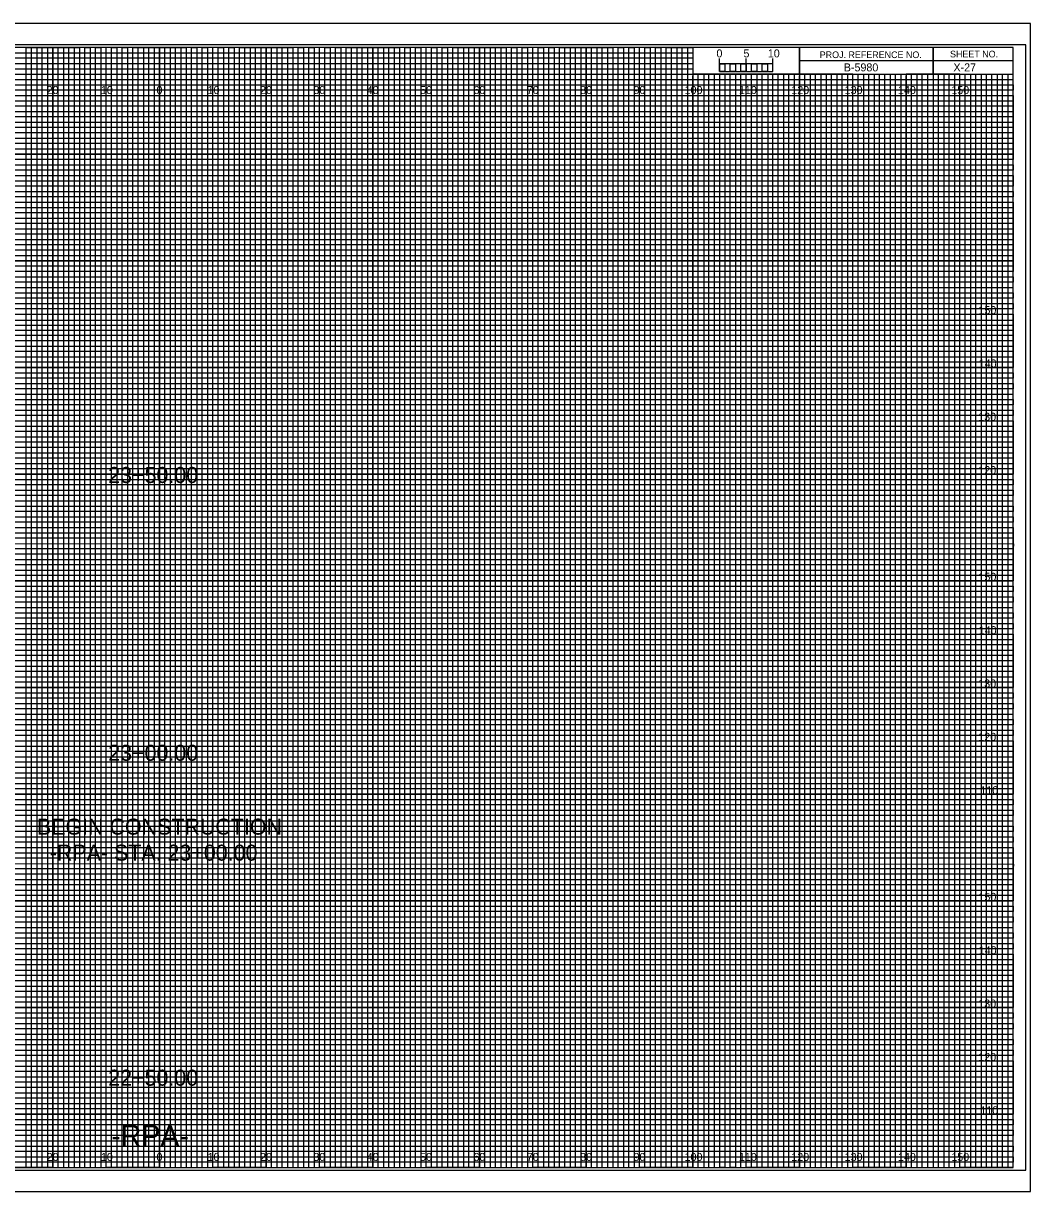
# Model space of a CAD drawing. Extents: x -13 to 323, y -5 to 1974.
# Drawn here: x 134.5 to 323.3, y 655.5 to 874.5 of the extents above; entities that cross this region are included whole.
import ezdxf

# ---------------------------------------------------------------- set-up
doc = ezdxf.new("R2010")
doc.units = 0
for name, color, linetype in [('Exist Cross Section Cell', 7, 'Continuous'), ('Exist XS Center Line Elevation Label', 7, 'Continuous'), ('Exist XS Ground Line', 7, 'Continuous'), ('Prop CMT Bridge Girder Bottom Critical Point Inside', 7, 'Continuous'), ('Prop CMT Guardrail Graphics', 7, 'Continuous'), ('Prop CMT Guardrail Widen Shoulder', 7, 'Continuous'), ('Prop CMT Pvmt Course 1', 7, 'Continuous'), ('Prop CMT Pvmt Course 2', 7, 'Continuous'), ('Prop CMT Pvmt Course 3', 7, 'Continuous'), ('Prop CMT Pvmt Surface', 7, 'Continuous'), ('Prop CMT Pvmt Surface Shoulder', 7, 'Continuous'), ('Prop CMT Shld Paved Course 1', 7, 'Continuous'), ('Prop CMT Shld Paved Course 2', 7, 'Continuous'), ('Prop CMT Shld Paved Course 3', 7, 'Continuous'), ('Prop CMT Slope Grass', 7, 'Continuous'), ('Prop CMT Subgrade Earthwork', 7, 'Continuous'), ('Scratch_Level_1', 7, 'Continuous')]:
    doc.layers.add(name, color=color, linetype=linetype)

msp = doc.modelspace()

# ---------------------------------------------------------------- linework, layer by layer
at = {"layer": 'Exist XS Center Line Elevation Label'}
for points in [[(125, 660), (135, 660), (135, 870), (145, 870), (145, 660), (155, 660), (155, 870), (165, 870), (165, 660), (175, 660), (175, 870), (185, 870), (185, 660), (195, 660), (195, 870), (205, 870), (205, 660), (215, 660), (215, 870), (225, 870), (225, 660), (235, 660), (235, 870), (245, 870), (245, 660), (255, 660), (255, 870), (259.93, 870), (260, 870), (260, 865), (264.99, 865), (264.99, 660), (275, 660), (275, 865), (285, 865), (285, 660), (295, 660), (295, 865), (305, 865), (305, 660), (315, 660), (315, 865)], [(0, 865), (275, 865)], [(0, 845), (320, 845), (320, 855), (0, 855)], [(0, 825), (320, 825), (320, 835), (0, 835)], [(0, 805), (320, 805), (320, 815), (0, 815)], [(0, 785), (320, 785), (320, 795), (0, 795)], [(0, 765), (320, 765), (320, 775), (0, 775)], [(0, 745), (320, 745), (320, 755), (0, 755)], [(0, 725), (320, 725), (320, 735), (0, 735)], [(0, 705), (320, 705), (320, 715), (0, 715)], [(0, 685), (320, 685), (320, 695), (0, 695)], [(0, 665), (320, 665), (320, 675), (0, 675)]]:
    msp.add_lwpolyline(points, dxfattribs=at)
at = {"layer": 'Exist XS Ground Line'}
for p, q in [((150, 870), (140, 870)), ((140, 870), (140, 660)), ((150, 660), (150, 870)), ((170, 870), (160, 870)), ((160, 870), (160, 660)), ((170, 660), (170, 870)), ((190, 870), (180, 870)), ((180, 870), (180, 660)), ((190, 660), (190, 870)), ((210, 870), (200, 870)), ((200, 870), (200, 660)), ((210, 660), (210, 870)), ((230, 870), (220, 870)), ((220, 870), (220, 660)), ((230, 660), (230, 870)), ((250, 870), (240, 870)), ((240, 870), (240, 660)), ((250, 660), (250, 870)), ((260, 870), (260, 660)), ((270, 660), (270, 865)), ((290, 865), (280, 865)), ((280, 865), (280, 660)), ((290, 660), (290, 865)), ((310, 865), (300, 865)), ((300, 865), (300, 660)), ((310, 660), (310, 865)), ((140, 660), (130, 660)), ((160, 660), (150, 660)), ((180, 660), (170, 660)), ((200, 660), (190, 660)), ((220, 660), (210, 660)), ((240, 660), (230, 660)), ((260, 660), (250, 660)), ((280, 660), (270, 660)), ((300, 660), (290, 660)), ((320, 660), (310, 660)), ((320, 660), (320, 660))]:
    msp.add_line(p, q, dxfattribs=at)
for points in [[(0, 860), (320, 860), (320, 850), (0, 850)], [(0, 840), (320, 840), (320, 830), (0, 830)], [(0, 820), (320, 820), (320, 810), (0, 810)], [(0, 800), (320, 800), (320, 790), (0, 790)], [(0, 780), (320, 780), (320, 770), (0, 770)], [(0, 760), (320, 760), (320, 750), (0, 750)], [(0, 740), (320, 740), (320, 730), (0, 730)], [(0, 720), (320, 720), (320, 710), (0, 710)], [(0, 700), (320, 700), (320, 690), (0, 690)], [(0, 680), (320, 680), (320, 670), (0, 670)]]:
    msp.add_lwpolyline(points, dxfattribs=at)
at = {"layer": 'Prop CMT Pvmt Course 2'}
for p, q in [((265, 865.49), (265, 867.9)), ((265, 866.9), (265, 867.9)), ((270, 865.49), (270, 867.9)), ((275, 865.49), (275, 867.9)), ((275, 866.9), (275, 867.9))]:
    msp.add_line(p, q, dxfattribs=at)
for points in [[(275, 866.9), (265, 866.9), (265, 865.49), (275, 865.49)], [(265, 866.9), (266, 866.9), (266, 865.49), (265, 865.49)], [(267, 866.9), (268, 866.9), (268, 865.49), (267, 865.49)], [(269, 866.9), (270, 866.9), (270, 865.49), (269, 865.49)], [(271, 866.9), (272, 866.9), (272, 865.49), (271, 865.49)], [(273, 866.9), (274, 866.9), (274, 865.49), (273, 865.49)]]:
    msp.add_lwpolyline(points, close=True, dxfattribs=at)
at = {"layer": 'Prop CMT Pvmt Course 3'}
msp.add_lwpolyline([(-13.4, 655.5), (323.3, 655.5), (323.3, 874.5), (-13.4, 874.5)], close=True, dxfattribs=at)
at = {"layer": 'Prop CMT Pvmt Surface'}
for p, q in [((140, 660), (140, 870)), ((150, 660), (150, 870)), ((160, 660), (160, 870)), ((170, 660), (170, 870)), ((180, 660), (180, 870)), ((190, 660), (190, 870)), ((200, 660), (200, 870)), ((210, 660), (210, 870)), ((220, 660), (220, 870)), ((230, 660), (230, 870)), ((240, 660), (240, 870)), ((250, 660), (250, 870)), ((260, 660), (260, 864.69)), ((270, 660), (270, 864.69)), ((280, 660), (280, 864.69)), ((290, 660), (290, 864.69)), ((300, 660), (300, 864.69)), ((310, 660), (310, 864.69)), ((0, 860), (320, 860)), ((0, 850), (320, 850)), ((0, 840), (320, 840)), ((0, 830), (320, 830)), ((0, 820), (320, 820)), ((0, 810), (320, 810)), ((0, 800), (320, 800)), ((0, 790), (320, 790)), ((0, 780), (320, 780)), ((0, 770), (320, 770)), ((0, 760), (320, 760)), ((0, 750), (320, 750)), ((0, 740), (320, 740)), ((0, 730), (320, 730)), ((0, 720), (320, 720)), ((0, 710), (320, 710)), ((0, 700), (320, 700)), ((0, 690), (320, 690)), ((0, 680), (320, 680)), ((0, 670), (320, 670))]:
    msp.add_line(p, q, dxfattribs=at)
at = {"layer": 'Prop CMT Pvmt Surface Shoulder'}
for p, q in [((323.3, 874.5), (-13.4, 874.5)), ((-13.4, 655.5), (323.3, 655.5))]:
    msp.add_line(p, q, dxfattribs=at)
at = {"layer": 'Prop CMT Shld Paved Course 1'}
for p, q in [((0, 869), (260, 869)), ((260, 867.98), (0, 867.98)), ((260, 869), (260, 867.98)), ((0, 867), (260, 867)), ((260, 865.89), (0, 865.89)), ((260, 867), (260, 865.89)), ((0, 864), (320, 864))]:
    msp.add_line(p, q, dxfattribs=at)
for points in [[(0, 863), (270, 863), (320, 863), (320, 862), (0, 862)], [(0, 861), (320, 861), (320, 859), (0, 859)], [(0, 858), (320, 858), (320, 857), (0, 856.98)], [(0, 856), (320, 856), (320, 854), (0, 854)], [(0, 853), (320, 853), (320, 852), (0, 852)], [(0, 851), (320, 851), (320, 849), (0, 849)], [(0, 848), (320, 848), (320, 847), (0, 847)], [(0, 846), (320, 846), (320, 844), (0, 844)], [(0, 843), (320, 843), (320, 842), (0, 842)], [(0, 841), (320, 841), (320, 839), (0, 839)], [(0, 838), (320, 838), (320, 837), (0, 837)], [(0, 836), (320, 836), (320, 833.95), (320, 833), (320, 832), (0, 832)], [(0, 834), (320, 834), (320, 833), (0, 833)], [(0, 831), (320, 831), (320, 829), (0, 829.03)], [(0, 829.03), (320, 829), (320, 828), (0, 828)], [(0, 827), (320, 827), (320, 826), (0, 826)], [(0, 824), (320, 824), (320, 823), (0, 823)], [(0, 822), (320, 822), (320, 821), (0, 821)], [(-0.07, 818.89), (320, 818.89), (320, 817.88), (-0.07, 817.88)], [(0, 817), (320, 817), (320, 816), (0, 816)], [(0, 814), (320, 814), (320, 813), (0, 813)], [(0, 812), (320, 812), (320, 811), (0, 811)], [(0, 809), (320, 809), (320, 808), (0, 808)], [(0, 807), (320, 807), (320, 806), (0, 806)], [(0, 804), (320, 804), (320, 803), (0, 803)], [(0, 802), (320, 802), (320, 801), (0, 801)], [(0, 799), (320, 799), (319.99, 797.98), (0, 798)], [(0, 797), (320, 797), (320, 796), (0, 796)], [(0, 794), (320, 794), (320, 793), (0, 793)], [(0, 792), (320, 792), (320, 791), (0, 791)], [(0, 789), (320, 789), (320, 788), (0, 788)], [(0, 787), (320, 787), (320, 786), (0, 786)], [(0, 784), (320, 784), (320, 783), (0, 783)], [(0, 782), (320, 782), (320, 781), (0, 781)], [(0, 779), (320, 779), (320, 778), (0, 778)], [(0, 776.99), (320.07, 776.91), (320, 776), (0, 776)], [(0, 774), (320, 774), (320, 773), (0, 773)], [(0, 772), (320, 772), (320, 771), (0, 771)], [(0, 769), (320, 769), (320, 768), (0, 768)], [(0, 767), (320, 767), (320, 766), (0, 766)], [(0, 764), (320, 764), (320, 763), (0, 763)], [(0, 762), (320, 762), (320, 761), (0, 761)], [(0, 759), (320, 759), (320, 758), (0, 758)], [(0, 757), (320, 757), (320, 756), (0, 756)], [(0, 754), (320, 754), (320, 753), (0, 753)], [(0, 752), (320, 752), (320, 751), (0, 751)], [(0, 749), (320, 749), (320, 748), (0, 748)], [(0, 747), (320, 747), (320, 746), (0, 746)], [(0, 744), (320, 744), (320, 743), (0, 743)], [(0, 742), (320, 742), (320, 741), (0, 741)], [(0, 739), (320, 739), (319.99, 737.98), (0, 738)], [(0, 737), (320, 737), (320, 736), (0, 736)], [(0, 734), (320, 734), (320, 733), (0, 733)], [(0, 732), (320, 732), (320, 731), (0, 731)], [(0, 729), (320, 729), (320, 728), (0, 728)], [(0, 727), (320, 727), (320, 726), (0, 726)], [(0, 724), (320, 724), (320, 723), (0, 723)], [(0, 722), (320, 722), (320, 721), (0, 721)], [(0, 719), (320, 719), (320, 718), (0, 718)], [(0, 716.99), (320.07, 716.91), (320, 716), (0, 716)], [(0, 714), (320, 714), (320, 713), (0, 713)], [(0, 712), (320, 712), (320, 711), (0, 711)], [(0, 709), (320, 709), (320, 708), (0, 708)], [(0, 707), (320, 707), (320, 706), (0, 706)], [(0, 704), (320, 704), (320, 703), (0, 703)], [(0, 702), (320, 702), (320, 701), (0, 701)], [(0, 699), (320, 699), (320, 698), (0, 698)], [(0, 697), (320, 697), (320, 696), (0, 696)], [(0, 694), (320, 694), (320, 693), (0, 693)], [(0, 692), (320, 692), (320, 691), (0, 691)], [(0, 689), (320, 689), (320, 688), (0, 688)], [(0, 687), (320, 687), (320, 686), (0, 686)], [(0, 684), (320, 684), (320, 683), (0, 683)], [(0, 682), (320, 682), (320, 681), (0, 681)], [(0, 679), (320, 679), (320, 678), (0, 678)], [(0, 677), (320, 677), (320, 676), (0, 676)], [(0, 674), (320, 674), (320, 673), (0, 673)], [(0, 672), (320, 672), (320, 671), (0, 671)], [(0, 669), (320, 669), (320, 668), (0, 668)], [(0, 667), (320, 667), (320, 666), (0, 666)], [(0, 664), (320, 664), (320, 663), (0, 663)], [(0, 662), (320, 662), (320, 661), (0, 661)]]:
    msp.add_lwpolyline(points, dxfattribs=at)
at = {"layer": 'Prop CMT Shld Paved Course 2'}
for p, q in [((305, 870), (305, 865)), ((305, 865), (305, 870)), ((280, 867.5), (280, 865)), ((320, 867.49), (280, 867.49)), ((280, 865), (320, 865))]:
    msp.add_line(p, q, dxfattribs=at)
for points in [[(320, 870), (0, 870), (0, 660), (320, 660)], [(280, 870), (260, 870), (260, 865.03), (280, 865.03)], [(320, 870), (280, 870), (280, 865), (320, 865)]]:
    msp.add_lwpolyline(points, close=True, dxfattribs=at)
at = {"layer": 'Prop CMT Shld Paved Course 3'}
for p, q in [((267, 865), (266.01, 865)), ((266.01, 865), (266.01, 660)), ((267, 660), (267, 865)), ((269, 865), (268, 865)), ((268, 865), (268, 660)), ((269, 660), (269, 865)), ((266.01, 660), (265, 660)), ((268, 660), (267, 660))]:
    msp.add_line(p, q, dxfattribs=at)
for points in [[(135, 660), (136, 660), (136, 870), (137, 870), (137, 660)], [(137, 660), (138, 660), (138, 870), (139, 870), (139, 660)], [(140, 660), (141, 660), (141, 870), (142, 870), (142, 660)], [(142, 660), (143, 660), (143, 870), (144, 870), (144, 660)], [(145, 660), (146, 660), (146, 870), (147, 870), (147, 660)], [(147, 660), (148, 660), (148, 870), (149, 870), (149, 660)], [(150, 660), (151, 660), (151, 870), (152, 870), (152, 660)], [(152, 660), (153, 660), (153, 870), (154, 870), (154, 660)], [(155, 660), (156, 660), (156, 870), (157, 870), (157, 660)], [(157, 660), (158, 660), (158, 870), (159, 870), (159, 660)], [(160, 660), (161, 660), (161, 870), (162, 870), (162, 660)], [(162, 660), (163, 660), (163, 870), (164, 870), (164, 660)], [(165, 660), (166, 660), (166, 870), (167, 870), (167, 660)], [(167, 660), (168, 660), (168, 870), (169, 870), (169, 660)], [(170, 660), (171, 660), (171, 870), (172, 870), (172, 660)], [(172, 660), (173, 660), (173, 870), (174, 870), (174, 660)], [(175, 660), (176, 660), (176, 870), (177, 870), (177, 660)], [(177, 660), (178, 660), (178, 870), (179, 870), (179, 660)], [(180, 660), (181, 660), (181, 870), (182, 870), (182, 660)], [(182, 660), (183, 660), (183, 870), (184, 870), (184, 660)], [(185, 660), (186, 660), (186, 870), (187, 870), (187, 660)], [(187, 660), (188, 660), (188, 870), (189, 870), (189, 660)], [(190, 660), (191, 660), (191, 870), (192, 870), (192, 660)], [(192, 660), (193, 660), (193, 870), (194, 870), (194, 660)], [(195, 660), (196, 660), (196, 870), (197, 870), (197, 660)], [(197, 660), (198, 660), (198, 870), (199, 870), (199, 660)], [(200, 660), (201, 660), (201, 870), (202, 870), (202, 660)], [(202, 660), (203, 660), (203, 870), (204, 870), (204, 660)], [(205, 660), (206, 660), (206, 870), (207, 870), (207, 660)], [(207, 660), (208, 660), (208, 870), (209, 870), (209, 660)], [(210, 660), (211, 660), (211, 870), (212, 870), (212, 660)], [(212, 660), (213, 660), (213, 870), (214, 870), (214, 660)], [(215, 660), (216, 660), (216, 870), (217, 870), (217, 660)], [(217, 660), (218, 660), (218, 870), (219, 870), (219, 660)], [(220, 660), (221, 660), (221, 870), (222, 870), (222, 660)], [(222, 660), (223, 660), (223, 870), (224, 870), (224, 660)], [(225, 660), (226, 660), (226, 870), (227, 870), (227, 660)], [(227, 660), (228, 660), (228, 870), (229, 870), (229, 660)], [(230, 660), (231, 660), (231, 870), (232, 870), (232, 660)], [(232, 660), (233, 660), (233, 870), (234, 870), (234, 660)], [(235, 660), (236, 660), (236, 870), (237, 870), (237, 660)], [(237, 660), (238, 660), (238, 870), (239, 870), (239, 660)], [(240, 660), (241, 660), (241, 870), (242, 870), (242, 660)], [(242, 660), (243, 660), (243, 870), (244, 870), (244, 660)], [(245, 660), (246, 660), (246, 870), (247, 870), (247, 660)], [(247, 660), (248, 660), (248, 870), (249, 870), (249, 660)], [(250, 660), (251, 660), (251, 870), (252, 870), (252, 660)], [(252, 660), (253, 660), (253, 870), (254, 870), (254, 660)], [(255, 660), (256, 660), (256, 870), (257, 870), (257, 660)], [(257, 660), (258, 660), (258, 870), (259, 870), (259, 660)], [(260, 660), (261, 660), (261, 865), (262.02, 865), (262.02, 660)], [(262, 660), (263, 660), (263, 865), (263.99, 865), (263.99, 660)], [(270, 660), (270.98, 660), (270.98, 865), (272, 865), (272, 660)], [(272, 660), (273, 660), (273, 865), (274.05, 865), (274.05, 660)], [(275, 660), (276, 660), (276, 865), (277, 865), (277, 660)], [(277, 660), (278, 660), (278, 865), (279, 865), (279, 660)], [(280, 660), (281, 660), (281, 865), (282, 865), (282, 660)], [(282, 660), (283, 660), (283, 865), (284, 865), (284, 660)], [(285, 660), (286, 660), (286, 865), (287, 865), (287, 660)], [(287, 660), (288, 660), (288, 865), (289, 865), (289, 660)], [(290, 660), (291, 660), (291, 865), (292, 865), (292, 660)], [(292, 660), (293, 660), (293, 865), (294, 865), (294, 660)], [(295, 660), (296, 660), (296, 865), (297, 865), (297, 660)], [(297, 660), (298, 660), (298, 865), (299, 865), (299, 660)], [(300, 660), (301, 660), (301, 865), (302, 865), (302, 660)], [(302, 660), (303, 660), (303, 865), (304, 865), (304, 660)], [(305, 660), (306, 660), (306, 865), (307, 865), (307, 660)], [(307, 660), (308, 660), (308, 865), (309, 865), (309, 660)], [(310, 660), (311, 660), (311, 865), (312, 865), (312, 660)], [(312, 660), (313, 660), (313, 865), (314, 865), (314, 660)], [(315, 660), (316, 660), (316, 865), (317, 865), (317, 660)], [(317, 660), (318, 660), (318, 865), (319, 865), (319, 660)]]:
    msp.add_lwpolyline(points, dxfattribs=at)
at = {"layer": 'Prop CMT Subgrade Earthwork'}
msp.add_lwpolyline([(-10.8, 659.5), (322.4, 659.5), (322.4, 870.5), (-10.8, 870.5)], close=True, dxfattribs=at)

# ---------------------------------------------------------------- texts
at = {"layer": 'Exist Cross Section Cell'}
for s, p in [('20', (138.86, 861.25)), ('10', (149.04, 861.25)), ('0', (159.45, 861.25)), ('0', (159.45, 861.25)), ('10', (169.04, 861.25)), ('20', (178.86, 861.25)), ('30', (188.86, 861.25)), ('40', (198.86, 861.25)), ('50', (208.86, 861.25)), ('60', (218.86, 861.25)), ('70', (228.86, 861.25)), ('80', (238.86, 861.25)), ('90', (248.86, 861.25)), ('100', (258.44, 861.25)), ('110', (268.62, 861.25)), ('120', (278.44, 861.25)), ('130', (288.44, 861.25)), ('140', (298.44, 861.25)), ('150', (308.44, 861.25)), ('20', (138.86, 661.25)), ('10', (149.04, 661.25)), ('0', (159.45, 661.25)), ('0', (159.45, 661.25)), ('10', (169.04, 661.25)), ('20', (178.86, 661.25)), ('30', (188.86, 661.25)), ('40', (198.86, 661.25)), ('50', (208.86, 661.25)), ('60', (218.86, 661.25)), ('70', (228.86, 661.25)), ('80', (238.86, 661.25)), ('90', (248.86, 661.25)), ('100', (258.44, 661.25)), ('110', (268.62, 661.25)), ('120', (278.44, 661.25)), ('130', (288.44, 661.25)), ('140', (298.44, 661.25)), ('150', (308.44, 661.25))]:
    msp.add_text(s, height=1.5, dxfattribs=at).set_placement(p)
at = {"layer": 'Prop CMT Bridge Girder Bottom Critical Point Inside'}
for s, p in [('5', (269.47, 868.12)), ('10', (274.04, 868.12))]:
    msp.add_text(s, height=1.5, dxfattribs=at).set_placement(p)
at = {"layer": 'Prop CMT Guardrail Graphics'}
msp.add_text('B-5980', height=1.5, dxfattribs=at).set_placement((288.28, 865.5))
at = {"layer": 'Prop CMT Guardrail Widen Shoulder'}
msp.add_text('X-27', height=1.5, dxfattribs=at).set_placement((308.83, 865.5))
at = {"layer": 'Prop CMT Pvmt Course 1'}
for s, p in [('150', (313.52, 820)), ('140', (313.57, 810)), ('130', (313.49, 800)), ('120', (313.5, 790)), ('150', (313.52, 770)), ('140', (313.57, 760)), ('130', (313.49, 750)), ('120', (313.5, 740)), ('110', (313.88, 730)), ('150', (313.52, 710)), ('140', (313.57, 700)), ('130', (313.49, 690)), ('120', (313.5, 680)), ('110', (313.88, 670))]:
    msp.add_text(s, height=1.5, dxfattribs=at).set_placement(p)
at = {"layer": 'Prop CMT Pvmt Course 2'}
msp.add_text('0', height=1.5, dxfattribs=at).set_placement((264.41, 868.12))
at = {"layer": 'Prop CMT Shld Paved Course 2'}
for s, p in [('PROJ. REFERENCE NO.', (283.77, 867.99)), ('SHEET NO.', (308.19, 868.12))]:
    msp.add_text(s, height=1.25, dxfattribs=at).set_placement(p)
at = {"layer": 'Prop CMT Slope Grass'}
for s, p in [('23+50.00', (150.41, 788.34)), ('23+00.00', (150.41, 736.27)), ('BEGIN CONSTRUCTION', (137.05, 722.42)), ('-RPA- STA. 23+00.00', (139.46, 717.54)), ('22+50.00', (150.41, 675.36))]:
    msp.add_text(s, height=3, dxfattribs=at).set_placement(p)
at = {"layer": 'Scratch_Level_1'}
msp.add_text('-RPA-', height=4, dxfattribs=at).set_placement((150.97, 664))

doc.saveas('drawing.dxf')
